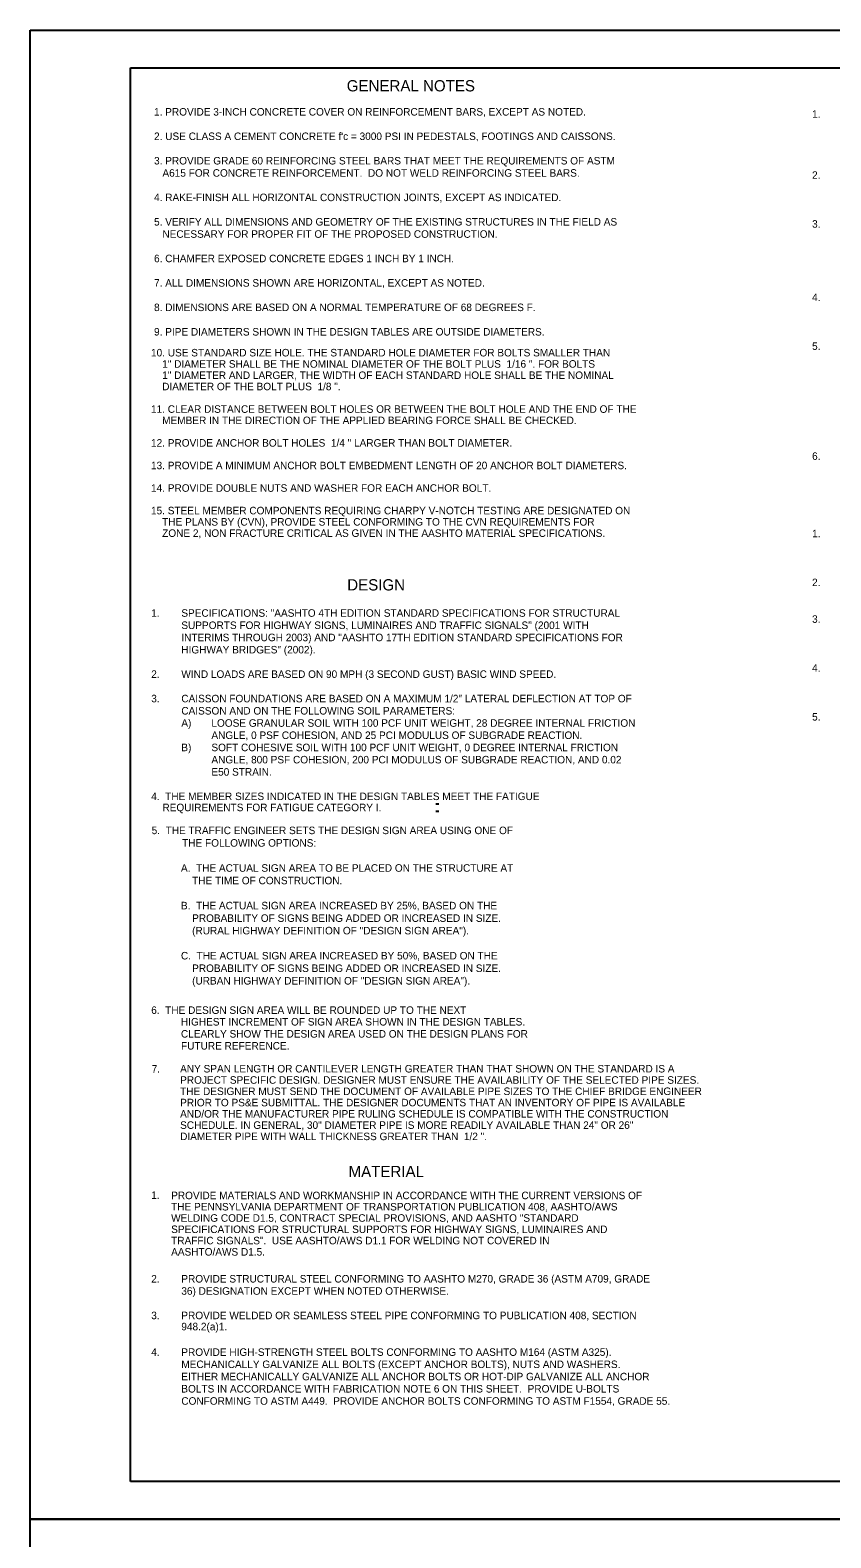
# Model space of a CAD drawing. Extents: x 640117 to 642655, y 297247 to 298435.
# Drawn here: x 640117 to 640437, y 297834 to 298435 of the extents above; entities that cross this region are included whole.
import ezdxf

# ---------------------------------------------------------------- set-up
doc = ezdxf.new("R2010")
doc.units = 0
for name, color, linetype in [('10', 7, 'Continuous'), ('2', 7, 'Continuous'), ('20', 7, 'Continuous'), ('53', 7, 'Continuous'), ('PLT-BNDY', 7, 'Continuous')]:
    doc.layers.add(name, color=color, linetype=linetype)

msp = doc.modelspace()

# ---------------------------------------------------------------- linework, layer by layer
at = {"layer": '2'}
for p, q in [((640157.46, 297856.46), (640157.46, 298420.46)), ((640157.46, 298420.46), (640943.46, 298420.46)), ((640943.46, 297856.46), (640157.46, 297856.46))]:
    msp.add_line(p, q, dxfattribs=at)
at = {"layer": '20'}
for p, q in [((640279.32, 298126.85), (640280.56, 298126.85)), ((640279.32, 298123.85), (640280.56, 298123.85))]:
    msp.add_line(p, q, dxfattribs=at)
at = {"layer": 'PLT-BNDY'}
for points in [[(640117.46, 298435.46), (640958.46, 298435.46), (640958.46, 297841.46), (640117.46, 297841.46)], [(640117.46, 297841.46), (640958.46, 297841.46), (640958.46, 297247.46), (640117.46, 297247.46)]]:
    msp.add_lwpolyline(points, close=True, dxfattribs=at)

# ---------------------------------------------------------------- texts
at = {"layer": '10'}
for s, height, p in [('10. USE STANDARD SIZE HOLE. THE STANDARD HOLE DIAMETER FOR BOLTS SMALLER THAN', 3, (640165.68, 298305.29)), ('    1" DIAMETER SHALL BE THE NOMINAL DIAMETER OF THE BOLT PLUS  1/16 ". FOR BOLTS', 3, (640165.68, 298300.79)), ('    1" DIAMETER AND LARGER, THE WIDTH OF EACH STANDARD HOLE SHALL BE THE NOMINAL', 3, (640165.68, 298296.29)), ('    DIAMETER OF THE BOLT PLUS  1/8 ".', 3, (640165.68, 298291.79)), ('11. CLEAR DISTANCE BETWEEN BOLT HOLES OR BETWEEN THE BOLT HOLE AND THE END OF THE', 3, (640165.68, 298282.79)), ('    MEMBER IN THE DIRECTION OF THE APPLIED BEARING FORCE SHALL BE CHECKED.', 3, (640165.68, 298278.29)), ('12. PROVIDE ANCHOR BOLT HOLES  1/4 " LARGER THAN BOLT DIAMETER.', 3, (640165.68, 298269.29)), ('13. PROVIDE A MINIMUM ANCHOR BOLT EMBEDMENT LENGTH OF 20 ANCHOR BOLT DIAMETERS.', 3, (640165.68, 298260.29)), ('14. PROVIDE DOUBLE NUTS AND WASHER FOR EACH ANCHOR BOLT.', 3, (640165.68, 298251.29)), ('15. STEEL MEMBER COMPONENTS REQUIRING CHARPY V-NOTCH TESTING ARE DESIGNATED ON ', 3, (640165.68, 298242.29)), ('    THE PLANS BY (CVN), PROVIDE STEEL CONFORMING TO THE CVN REQUIREMENTS FOR ', 3, (640165.68, 298237.79)), ('    ZONE 2, NON FRACTURE CRITICAL AS GIVEN IN THE AASHTO MATERIAL SPECIFICATIONS.', 3, (640165.68, 298233.29)), ('7.  ', 2.999, (640165.94, 298019.57)), ('ANY SPAN LENGTH OR CANTILEVER LENGTH GREATER THAN THAT SHOWN ON THE STANDARD IS A ', 3.0001, (640177.3, 298019.62)), ('THE DESIGNER MUST SEND THE DOCUMENT OF AVAILABLE PIPE SIZES TO THE CHIEF BRIDGE ENGINEER', 3.0001, (640177.3, 298010.62)), ('PROJECT SPECIFIC DESIGN. DESIGNER MUST ENSURE THE AVAILABILITY OF THE SELECTED PIPE SIZES.', 3.0001, (640177.3, 298015.12)), ('PRIOR TO PS&E SUBMITTAL. THE DESIGNER DOCUMENTS THAT AN INVENTORY OF PIPE IS AVAILABLE ', 3.0001, (640177.3, 298006.12)), ('AND/OR THE MANUFACTURER PIPE RULING SCHEDULE IS COMPATIBLE WITH THE CONSTRUCTION ', 3.0001, (640177.3, 298001.62)), ('SCHEDULE. IN GENERAL, 30" DIAMETER PIPE IS MORE READILY AVAILABLE THAN 24" OR 26" ', 3.0001, (640177.3, 297997.12)), ('DIAMETER PIPE WITH WALL THICKNESS GREATER THAN  1/2 ".', 3.0001, (640177.3, 297992.62)), ('  PROVIDE MATERIALS AND WORKMANSHIP IN ACCORDANCE WITH THE CURRENT VERSIONS OF', 3.0001, (640171.49, 297969.06)), ('  THE PENNSYLVANIA DEPARTMENT OF TRANSPORTATION PUBLICATION 408, AASHTO/AWS', 3.0001, (640171.49, 297964.56)), ('  WELDING CODE D1.5, CONTRACT SPECIAL PROVISIONS, AND AASHTO "STANDARD', 3.0001, (640171.49, 297960.06)), ('  TRAFFIC SIGNALS".  USE AASHTO/AWS D1.1 FOR WELDING NOT COVERED IN', 3.0001, (640171.49, 297951.06)), ('  SPECIFICATIONS FOR STRUCTURAL SUPPORTS FOR HIGHWAY SIGNS, LUMINAIRES AND', 3.0001, (640171.49, 297955.56)), ('  AASHTO/AWS D1.5.', 3.0001, (640171.49, 297946.56))]:
    msp.add_text(s, height=height, dxfattribs=at).set_placement(p)
for s, height, p in [('5.  THE TRAFFIC ENGINEER SETS THE DESIGN SIGN AREA USING ONE OF ', 2.9993, (640165.94, 298114.7)), ('THE FOLLOWING OPTIONS:', 2.9993, (640178.11, 298109.7)), ('A.  THE ACTUAL SIGN AREA TO BE PLACED ON THE STRUCTURE AT', 2.9993, (640177.63, 298099.7)), ('    THE TIME OF CONSTRUCTION.', 2.9993, (640177.63, 298094.7)), ('B.  THE ACTUAL SIGN AREA INCREASED BY 25%, BASED ON THE', 2.9993, (640177.63, 298084.7)), ('    PROBABILITY OF SIGNS BEING ADDED OR INCREASED IN SIZE.', 2.9993, (640177.63, 298079.7)), ('    (RURAL HIGHWAY DEFINITION OF "DESIGN SIGN AREA").', 2.9993, (640177.63, 298074.71)), ('C.  THE ACTUAL SIGN AREA INCREASED BY 50%, BASED ON THE', 2.9993, (640177.63, 298064.71)), ('    PROBABILITY OF SIGNS BEING ADDED OR INCREASED IN SIZE.', 2.9993, (640177.63, 298059.71)), ('    (URBAN HIGHWAY DEFINITION OF "DESIGN SIGN AREA").', 2.9993, (640177.63, 298054.71)), ('6.  THE DESIGN SIGN AREA WILL BE ROUNDED UP TO THE NEXT', 3.0004, (640165.77, 298042.99)), ('HIGHEST INCREMENT OF SIGN AREA SHOWN IN THE DESIGN TABLES.', 3.0004, (640177.63, 298038.35)), ('CLEARLY SHOW THE DESIGN AREA USED ON THE DESIGN PLANS FOR', 3.0004, (640177.63, 298033.53)), ('FUTURE REFERENCE.', 3.0004, (640177.67, 298028.76))]:
    msp.add_text(s, height=height, rotation=360, dxfattribs=at).set_placement(p)
at = {"layer": '53'}
for s, height, p in [('GENERAL NOTES', 4.5, (640243.79, 298411.02)), (' 1. PROVIDE 3-INCH CONCRETE COVER ON REINFORCEMENT BARS, EXCEPT AS NOTED.', 3, (640165.78, 298401.37)), ('1.', 3, (640429.46, 298400.52)), (" 2. USE CLASS A CEMENT CONCRETE f'c = 3000 PSI IN PEDESTALS, FOOTINGS AND CAISSONS.", 3, (640165.78, 298391.62)), (' 3. PROVIDE GRADE 60 REINFORCING STEEL BARS THAT MEET THE REQUIREMENTS OF ASTM ', 3, (640165.78, 298381.87)), ('    A615 FOR CONCRETE REINFORCEMENT.  DO NOT WELD REINFORCING STEEL BARS.', 3, (640165.78, 298376.99)), ('2.', 3, (640429.46, 298376.14)), (' 4. RAKE-FINISH ALL HORIZONTAL CONSTRUCTION JOINTS, EXCEPT AS INDICATED.', 3, (640165.78, 298367.24)), (' 5. VERIFY ALL DIMENSIONS AND GEOMETRY OF THE EXISTING STRUCTURES IN THE FIELD AS ', 3, (640165.78, 298357.49)), ('3.', 3, (640429.46, 298356.64)), ('    NECESSARY FOR PROPER FIT OF THE PROPOSED CONSTRUCTION.', 3, (640165.78, 298352.62)), (' 6. CHAMFER EXPOSED CONCRETE EDGES 1 INCH BY 1 INCH.', 3, (640165.78, 298342.87)), (' 7. ALL DIMENSIONS SHOWN ARE HORIZONTAL, EXCEPT AS NOTED.', 3, (640165.78, 298333.12)), (' 8. DIMENSIONS ARE BASED ON A NORMAL TEMPERATURE OF 68 DEGREES F.', 3, (640165.78, 298323.37)), ('4.', 3, (640429.46, 298327.39)), (' 9. PIPE DIAMETERS SHOWN IN THE DESIGN TABLES ARE OUTSIDE DIAMETERS.', 3, (640165.78, 298313.62)), ('5.', 3, (640429.46, 298307.89)), ('6.', 3, (640429.46, 298264.02)), ('1.', 3, (640429.46, 298233.14)), ('DESIGN', 4.5, (640243.98, 298211.92)), ('2.', 3, (640429.46, 298213.64)), ('1.', 3, (640165.78, 298201.42)), ('SPECIFICATIONS: "AASHTO 4TH EDITION STANDARD SPECIFICATIONS FOR STRUCTURAL ', 3, (640177.78, 298201.42)), ('SUPPORTS FOR HIGHWAY SIGNS, LUMINAIRES AND TRAFFIC SIGNALS" (2001 WITH ', 3, (640177.78, 298196.54)), ('3.', 3, (640429.46, 298199.01)), ('INTERIMS THROUGH 2003) AND "AASHTO 17TH EDITION STANDARD SPECIFICATIONS FOR ', 3, (640177.78, 298191.67)), ('HIGHWAY BRIDGES" (2002).', 3, (640177.78, 298186.79)), ('4.', 3, (640429.46, 298179.51)), ('2.', 3, (640165.78, 298177.04)), ('WIND LOADS ARE BASED ON 90 MPH (3 SECOND GUST) BASIC WIND SPEED.', 3, (640177.78, 298177.04)), ('3.', 3, (640165.78, 298167.29)), ('CAISSON FOUNDATIONS ARE BASED ON A MAXIMUM 1/2" LATERAL DEFLECTION AT TOP OF ', 3, (640177.78, 298167.29)), ('CAISSON AND ON THE FOLLOWING SOIL PARAMETERS:', 3, (640177.78, 298162.42)), ('A)', 3, (640177.78, 298157.54)), ('LOOSE GRANULAR SOIL WITH 100 PCF UNIT WEIGHT, 28 DEGREE INTERNAL FRICTION ', 3, (640189.78, 298157.54)), ('5.', 3, (640429.46, 298160.01)), ('ANGLE, 0 PSF COHESION, AND 25 PCI MODULUS OF SUBGRADE REACTION.', 3, (640189.78, 298152.67)), ('B)', 3, (640177.78, 298147.79)), ('ANGLE, 800 PSF COHESION, 200 PCI MODULUS OF SUBGRADE REACTION, AND 0.02 ', 3, (640189.78, 298142.92)), ('SOFT COHESIVE SOIL WITH 100 PCF UNIT WEIGHT, 0 DEGREE INTERNAL FRICTION ', 3, (640189.78, 298147.79)), ('E50 STRAIN.', 3, (640189.78, 298138.04)), ('4.  THE MEMBER SIZES INDICATED IN THE DESIGN TABLES MEET THE FATIGUE', 3, (640165.78, 298128.29)), ('    REQUIREMENTS FOR FATIGUE CATEGORY I.', 3, (640165.78, 298123.85)), ('MATERIAL', 4.5, (640244.51, 297977.86)), ('1.', 3, (640165.78, 297969.16)), ('2.', 3, (640165.78, 297935.81)), ('PROVIDE STRUCTURAL STEEL CONFORMING TO AASHTO M270, GRADE 36 (ASTM A709, GRADE ', 3, (640177.78, 297935.81)), ('36) DESIGNATION EXCEPT WHEN NOTED OTHERWISE.', 3, (640177.78, 297930.94)), ('3.', 3, (640165.78, 297921.19)), ('PROVIDE WELDED OR SEAMLESS STEEL PIPE CONFORMING TO PUBLICATION 408, SECTION ', 3, (640177.78, 297921.19)), ('948.2(a)1.', 3, (640177.78, 297916.75)), ('4.', 3, (640165.78, 297906.56)), ('PROVIDE HIGH-STRENGTH STEEL BOLTS CONFORMING TO AASHTO M164 (ASTM A325).  ', 3, (640177.78, 297906.56)), ('MECHANICALLY GALVANIZE ALL BOLTS (EXCEPT ANCHOR BOLTS), NUTS AND WASHERS.  ', 3, (640177.78, 297901.69)), ('EITHER MECHANICALLY GALVANIZE ALL ANCHOR BOLTS OR HOT-DIP GALVANIZE ALL ANCHOR ', 3, (640177.78, 297896.81)), ('BOLTS IN ACCORDANCE WITH FABRICATION NOTE 6 ON THIS SHEET.  PROVIDE U-BOLTS ', 3, (640177.78, 297891.94)), ('CONFORMING TO ASTM A449.  PROVIDE ANCHOR BOLTS CONFORMING TO ASTM F1554, GRADE 55. ', 3, (640177.78, 297887.06))]:
    msp.add_text(s, height=height, dxfattribs=at).set_placement(p)

doc.saveas('drawing.dxf')
